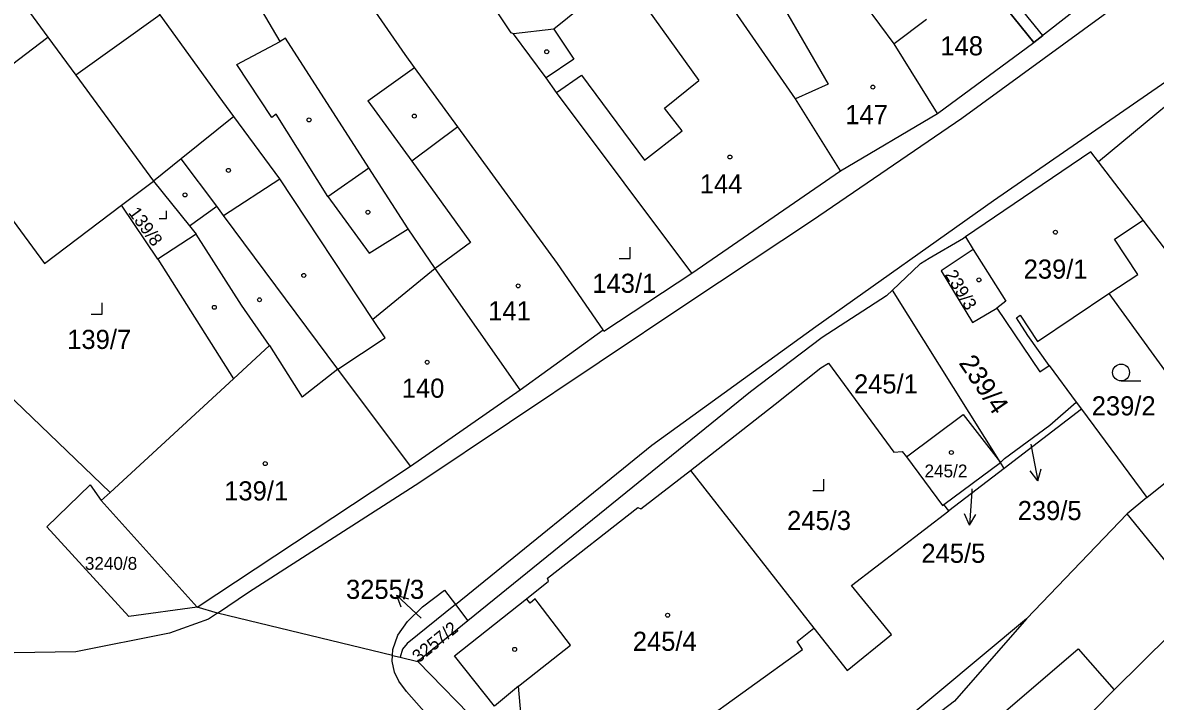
# Model space of a CAD drawing. Extents: x -600849 to -599899, y -1204328 to -1203436.
# Drawn here: x -600587.3 to -600486.5, y -1203787.4 to -1203727 of the extents above; entities that cross this region are included whole.
import ezdxf

# ---------------------------------------------------------------- set-up
doc = ezdxf.new("R2010")
doc.units = 0
for name, color, linetype in [('Vrstva 1', 7, 'Continuous'), ('Vrstva 13', 7, 'Continuous'), ('Vrstva 2', 7, 'Continuous'), ('Vrstva 3', 7, 'Continuous'), ('Vrstva 4', 7, 'Continuous'), ('Vrstva 5', 7, 'Continuous'), ('Vrstva 7', 7, 'Continuous')]:
    doc.layers.add(name, color=color, linetype=linetype)

msp = doc.modelspace()

# ---------------------------------------------------------------- linework, layer by layer
at = {"layer": 'Vrstva 1'}
for p, q in [((-600489.46, -1203722.64), (-600497.34, -1203728.8)), ((-600505.91, -1203735.13), (-600497.34, -1203728.8)), ((-600514.56, -1203740.22), (-600505.91, -1203735.13)), ((-600492.26, -1203738.52), (-600503.41, -1203746.1)), ((-600491.59, -1203739.41), (-600492.26, -1203738.52)), ((-600527.78, -1203749.32), (-600514.56, -1203740.22)), ((-600578.52, -1203743.27), (-600575.69, -1203741.13)), ((-600575.29, -1203748.08), (-600578.52, -1203743.27)), ((-600503.41, -1203746.1), (-600503.6, -1203746.23)), ((-600503.41, -1203746.1), (-600502.75, -1203747.21)), ((-600535.67, -1203754.37), (-600539.73, -1203748.47)), ((-600507.5, -1203748.53), (-600509.92, -1203750.84)), ((-600509.92, -1203750.84), (-600510.46, -1203751.35)), ((-600500.32, -1203766.15), (-600509.92, -1203750.84)), ((-600543.06, -1203759.7), (-600535.67, -1203754.37)), ((-600495.99, -1203757.53), (-600493.58, -1203760.78)), ((-600589.69, -1203759.08), (-600579.54, -1203768.84)), ((-600552.82, -1203766.5), (-600543.06, -1203759.7)), ((-600493.58, -1203760.78), (-600493.1, -1203761.43)), ((-600493.1, -1203761.43), (-600499.98, -1203766.69)), ((-600493.1, -1203761.43), (-600487.29, -1203769.27)), ((-600487.29, -1203769.27), (-600482.45, -1203765.39)), ((-600571.79, -1203779.02), (-600552.82, -1203766.5)), ((-600505.36, -1203769.9), (-600500.32, -1203766.15)), ((-600499.98, -1203766.69), (-600504.92, -1203770.47)), ((-600499.98, -1203766.69), (-600500.32, -1203766.15)), ((-600567.24, -1203777.68), (-600551.99, -1203767.9)), ((-600579.54, -1203768.84), (-600580.33, -1203769.54)), ((-600580.33, -1203769.54), (-600571.79, -1203779.02)), ((-600504.92, -1203770.47), (-600505.36, -1203769.9)), ((-600487.29, -1203769.27), (-600489.05, -1203770.73)), ((-600489.05, -1203770.73), (-600498, -1203780.07)), ((-600482.55, -1203778.7), (-600489.05, -1203770.73)), ((-600569.99, -1203779.55), (-600567.24, -1203777.68)), ((-600548.81, -1203778.78), (-600553.1, -1203782.26)), ((-600548.81, -1203778.78), (-600547.7, -1203780.24)), ((-600569.99, -1203779.55), (-600571.79, -1203779.02)), ((-600554.41, -1203783.32), (-600569.99, -1203779.55)), ((-600547.7, -1203780.24), (-600552.16, -1203783.86)), ((-600554.41, -1203783.32), (-600554.39, -1203782.8)), ((-600554.43, -1203783.82), (-600554.41, -1203783.32)), ((-600554.41, -1203783.32), (-600553.73, -1203783.48)), ((-600553.73, -1203783.48), (-600552.16, -1203783.86)), ((-600552.16, -1203783.86), (-600539.04, -1203797.3))]:
    msp.add_line(p, q, dxfattribs=at)
for points in [[(-600516.74, -1203754.05), (-600500.93, -1203742.85), (-600482.23, -1203729.97), (-600472.33, -1203722.55), (-600463.46, -1203715.87), (-600456.83, -1203710.5), (-600450.71, -1203706.1), (-600424.21, -1203680.79), (-600406.92, -1203664.19), (-600381.77, -1203639.93), (-600378.09, -1203636.25), (-600365.25, -1203624.15), (-600362.86, -1203622.3), (-600356.33, -1203617.3), (-600346.34, -1203609.78), (-600334.21, -1203600.46), (-600309.35, -1203581.63), (-600259.57, -1203537.67), (-600253.46, -1203531.77)], [(-600514.56, -1203740.22), (-600518.55, -1203733.82), (-600530.21, -1203716.96), (-600533.65, -1203713.17), (-600537.95, -1203708.73)], [(-600503.75, -1203735.54), (-600478.6, -1203717.19), (-600468.32, -1203708.8)], [(-600505.91, -1203735.13), (-600509.78, -1203728.93), (-600517.42, -1203718.58), (-600525.04, -1203709.94)], [(-600568.53, -1203735.4), (-600569.85, -1203733.61), (-600575.09, -1203726.34), (-600576.89, -1203723.85), (-600584.83, -1203712.83)], [(-600593, -1203717.54), (-600592.53, -1203718.19), (-600585.08, -1203728.33), (-600582.6, -1203731.71), (-600575.69, -1203741.13)], [(-600527.78, -1203749.32), (-600539.81, -1203733.24), (-600540.75, -1203731.96), (-600543.64, -1203728.03), (-600543.86, -1203727.95), (-600545.87, -1203724.89), (-600548.94, -1203720.23)], [(-600497.34, -1203728.8), (-600501.57, -1203723.53), (-600501.74, -1203723.36)], [(-600603.56, -1203723.74), (-600585.38, -1203748.47), (-600578.52, -1203743.27)], [(-600539.73, -1203748.47), (-600548.6, -1203736.31), (-600552.45, -1203731.03), (-600553.3, -1203729.87), (-600556.63, -1203725.05)], [(-600543.06, -1203759.7), (-600550.62, -1203748.91), (-600553.02, -1203745.37), (-600556.53, -1203739.96), (-600563.93, -1203728.43), (-600564.41, -1203728.72), (-600566.07, -1203725.89)], [(-600480.16, -1203730.41), (-600480.34, -1203730.12), (-600491.59, -1203739.41)], [(-600568.53, -1203735.4), (-600573.22, -1203739.15), (-600575.69, -1203741.13)], [(-600552.82, -1203766.5), (-600559.27, -1203757.85), (-600555.06, -1203755.08), (-600556.15, -1203753.43), (-600564.44, -1203740.94), (-600568.53, -1203735.4)], [(-600551.99, -1203767.9), (-600528.03, -1203751.91), (-600517.03, -1203744.62), (-600503.75, -1203735.54)], [(-600478.21, -1203757.62), (-600484.29, -1203748.96), (-600487.61, -1203744.61), (-600491.59, -1203739.41)], [(-600575.69, -1203741.13), (-600572.49, -1203745.1), (-600571.89, -1203745.84), (-600575.29, -1203748.08)], [(-600503.6, -1203746.23), (-600506.65, -1203748.02), (-600507.43, -1203748.48), (-600507.5, -1203748.53)], [(-600502.75, -1203747.21), (-600505.6, -1203749.1), (-600502.81, -1203753.71), (-600500.62, -1203752.42)], [(-600502.75, -1203747.21), (-600499.84, -1203751.82), (-600500.62, -1203752.42)], [(-600575.29, -1203748.08), (-600568.56, -1203758.71), (-600579.54, -1203768.84)], [(-600535.67, -1203754.37), (-600535.6, -1203754.49), (-600527.78, -1203749.32)], [(-600510.46, -1203751.35), (-600516.19, -1203755.04), (-600522.55, -1203759.86), (-600547.7, -1203780.24)], [(-600495.99, -1203757.53), (-600497.89, -1203754.85), (-600498.89, -1203753.29), (-600498.57, -1203753.07), (-600497.03, -1203755.41), (-600490.66, -1203751.13), (-600481.08, -1203764.32)], [(-600500.62, -1203752.42), (-600496.82, -1203758.09), (-600495.99, -1203757.53)], [(-600548.81, -1203778.78), (-600531.35, -1203764.63), (-600516.74, -1203754.05)], [(-600527.88, -1203766.86), (-600520.35, -1203760.97), (-600516.31, -1203757.75), (-600515.61, -1203757.32), (-600509.8, -1203765.23), (-600509.05, -1203765.18), (-600508.68, -1203765.66)], [(-600500.32, -1203766.15), (-600499.96, -1203765.81), (-600495.92, -1203762.84), (-600493.58, -1203760.78)], [(-600508.68, -1203765.66), (-600503.63, -1203761.88), (-600500.32, -1203766.15)], [(-600508.68, -1203765.66), (-600505.46, -1203769.98), (-600505.36, -1203769.9)], [(-600537.66, -1203796.41), (-600542.87, -1203789.77), (-600543.19, -1203786.06), (-600545.34, -1203787.84), (-600548.91, -1203783.34), (-600542.5, -1203778.28), (-600540.53, -1203776.7), (-600540.63, -1203776.45), (-600532.58, -1203770.15), (-600532.31, -1203770.28), (-600527.88, -1203766.86)], [(-600527.88, -1203766.86), (-600516.91, -1203780.89), (-600513.96, -1203784.67), (-600510.01, -1203781.45), (-600513.57, -1203777.09), (-600504.92, -1203770.47)], [(-600571.79, -1203779.02), (-600577.89, -1203779.86), (-600585.18, -1203771.89), (-600581.32, -1203768.16), (-600580.33, -1203769.54)], [(-600554.39, -1203782.8), (-600553.93, -1203781.52), (-600553.09, -1203780.31), (-600551.73, -1203778.99), (-600549.78, -1203777.5), (-600548.81, -1203778.78)], [(-600482.55, -1203778.7), (-600485.2, -1203781.47), (-600490.18, -1203786.39), (-600492.01, -1203788.21), (-600491.04, -1203789.24), (-600495.44, -1203792.84)], [(-600569.99, -1203779.55), (-600570.79, -1203780.08), (-600574.26, -1203781.35), (-600582.58, -1203783), (-600588.08, -1203783.09), (-600592.09, -1203782.35), (-600596.07, -1203781.08)], [(-600498, -1203780.07), (-600504.41, -1203787.38), (-600510.05, -1203791.68), (-600522.57, -1203801.02), (-600530.25, -1203807.86)], [(-600498, -1203780.07), (-600509.83, -1203789.94), (-600530.22, -1203805.9)], [(-600553.1, -1203782.26), (-600553.51, -1203782.76), (-600553.73, -1203783.48)], [(-600550.94, -1203789.04), (-600553.16, -1203786.52), (-600553.85, -1203785.62), (-600554.23, -1203784.82), (-600554.43, -1203783.82)]]:
    msp.add_lwpolyline(points, dxfattribs=at)
at = {"layer": 'Vrstva 13'}
msp.add_lwpolyline([(-600523.58, -1203699.44), (-600519.95, -1203703.04), (-600518.02, -1203704.91), (-600507.31, -1203717.65), (-600501.74, -1203723.36), (-600501.57, -1203723.53), (-600497.34, -1203728.8), (-600496.55, -1203728.18), (-600500.97, -1203722.73), (-600506.54, -1203717.01), (-600517.25, -1203704.27), (-600519.34, -1203702.25), (-600522.88, -1203698.72)], close=True, dxfattribs=at)
at = {"layer": 'Vrstva 3'}
for p, q in [((-600575.18, -1203744.45), (-600574.51, -1203744.45)), ((-600574.51, -1203744.45), (-600574.51, -1203743.78)), ((-600533.25, -1203748.01), (-600533.25, -1203747.01)), ((-600534.25, -1203748.01), (-600533.25, -1203748.01)), ((-600580.24, -1203752.97), (-600580.24, -1203751.97)), ((-600581.24, -1203752.97), (-600580.24, -1203752.97)), ((-600489.58, -1203758.91), (-600487.83, -1203758.91)), ((-600516.02, -1203768.65), (-600516.02, -1203767.65)), ((-600517.02, -1203768.65), (-600516.02, -1203768.65))]:
    msp.add_line(p, q, dxfattribs=at)
msp.add_circle((-600489.58, -1203758.16), 0.75, dxfattribs=at)
at = {"layer": 'Vrstva 4'}
for p, q in [((-600533.96, -1203722.68), (-600540.06, -1203727.63)), ((-600533.96, -1203722.68), (-600527.15, -1203732.19)), ((-600519.9, -1203725.2), (-600515.63, -1203732.52)), ((-600575.09, -1203726.34), (-600582.6, -1203731.71)), ((-600506.88, -1203726.75), (-600509.78, -1203728.93)), ((-600591.95, -1203733.56), (-600585.08, -1203728.33)), ((-600540.06, -1203727.63), (-600543.64, -1203728.03)), ((-600540.06, -1203727.63), (-600538.27, -1203730.29)), ((-600568.26, -1203730.77), (-600564.41, -1203728.72)), ((-600538.27, -1203730.29), (-600540.75, -1203731.96)), ((-600565.14, -1203735.49), (-600568.26, -1203730.77)), ((-600556.6, -1203733.98), (-600552.45, -1203731.03)), ((-600539.81, -1203733.24), (-600537.59, -1203731.71)), ((-600537.59, -1203731.71), (-600532, -1203739.27)), ((-600530.22, -1203734.64), (-600527.15, -1203732.19)), ((-600515.63, -1203732.52), (-600518.55, -1203733.82)), ((-600556.6, -1203733.98), (-600552.7, -1203739.37)), ((-600528.65, -1203736.65), (-600530.22, -1203734.64)), ((-600564.76, -1203735.17), (-600565.14, -1203735.49)), ((-600560.17, -1203742.51), (-600564.76, -1203735.17)), ((-600548.6, -1203736.31), (-600552.7, -1203739.37)), ((-600532, -1203739.27), (-600528.65, -1203736.65)), ((-600570.05, -1203743.37), (-600573.22, -1203739.15)), ((-600552.7, -1203739.37), (-600547.47, -1203746.6)), ((-600560.17, -1203742.51), (-600556.53, -1203739.96)), ((-600569.45, -1203744.18), (-600564.44, -1203740.94)), ((-600560.17, -1203742.51), (-600556.49, -1203747.54)), ((-600572.49, -1203745.1), (-600570.05, -1203743.37)), ((-600569.45, -1203744.18), (-600570.05, -1203743.37)), ((-600559.27, -1203757.85), (-600569.45, -1203744.18)), ((-600490.16, -1203746.3), (-600487.61, -1203744.61)), ((-600556.49, -1203747.54), (-600553.02, -1203745.37)), ((-600567.86, -1203752.16), (-600571.89, -1203745.84)), ((-600547.47, -1203746.6), (-600550.62, -1203748.91)), ((-600488.09, -1203749.43), (-600490.16, -1203746.3)), ((-600550.62, -1203748.91), (-600556.15, -1203753.43)), ((-600490.66, -1203751.13), (-600488.09, -1203749.43)), ((-600565.37, -1203755.76), (-600567.86, -1203752.16)), ((-600568.56, -1203758.71), (-600565.37, -1203755.76)), ((-600565.37, -1203755.76), (-600562.45, -1203760.35)), ((-600559.27, -1203757.85), (-600562.45, -1203760.35)), ((-600542.17, -1203778.66), (-600542.5, -1203778.28)), ((-600541.73, -1203778.28), (-600542.17, -1203778.66)), ((-600541.46, -1203778.63), (-600541.73, -1203778.28)), ((-600538.56, -1203782.39), (-600541.46, -1203778.63)), ((-600518.4, -1203782.09), (-600516.91, -1203780.89)), ((-600543.19, -1203786.06), (-600538.56, -1203782.39)), ((-600530.25, -1203791.64), (-600517.94, -1203782.8)), ((-600517.94, -1203782.8), (-600518.4, -1203782.09)), ((-600501.31, -1203789.51), (-600493.4, -1203782.72)), ((-600493.4, -1203782.72), (-600490.18, -1203786.39))]:
    msp.add_line(p, q, dxfattribs=at)
at = {"layer": 'Vrstva 5'}
for centre in [(-600540.69, -1203729.63), (-600511.67, -1203732.77), (-600561.84, -1203735.69), (-600552.47, -1203735.35), (-600524.39, -1203738.99), (-600569.01, -1203740.18), (-600572.88, -1203742.36), (-600556.6, -1203743.9), (-600495.42, -1203745.68), (-600562.31, -1203749.52), (-600502.23, -1203749.92), (-600543.23, -1203750.45), (-600566.25, -1203751.69), (-600570.27, -1203752.36), (-600551.33, -1203757.24), (-600504.68, -1203765.27), (-600565.74, -1203766.26), (-600529.93, -1203779.74), (-600543.54, -1203782.78)]:
    msp.add_circle(centre, 0.175, dxfattribs=at)
at = {"layer": 'Vrstva 7'}
for p, q in [((-600497.62, -1203764.53), (-600497.56, -1203764.85)), ((-600497.56, -1203764.85), (-600496.99, -1203767.8)), ((-600496.99, -1203767.8), (-600496.69, -1203766.72)), ((-600496.99, -1203767.8), (-600497.67, -1203766.91)), ((-600502.87, -1203768.75), (-600503.08, -1203771.74)), ((-600502.85, -1203768.49), (-600502.87, -1203768.75)), ((-600503.08, -1203771.74), (-600503.51, -1203770.71)), ((-600503.08, -1203771.74), (-600502.51, -1203770.78)), ((-600551.87, -1203780.01), (-600554.07, -1203777.96)), ((-600554.07, -1203777.96), (-600552.99, -1203778.28)), ((-600554.07, -1203777.96), (-600553.67, -1203779.01))]:
    msp.add_line(p, q, dxfattribs=at)

# ---------------------------------------------------------------- texts
at = {"layer": 'Vrstva 2'}
for s, height, p in [('148', 1.7, (-600505.66, -1203729.95)), ('147', 1.7, (-600514.12, -1203736.07)), ('144', 1.7, (-600527.07, -1203742.23)), ('239/1', 1.7, (-600498.25, -1203749.81)), ('143/1', 1.7, (-600536.63, -1203751.07)), ('141', 1.7, (-600545.9, -1203753.52)), ('139/7', 1.7, (-600583.36, -1203756.06)), ('140', 1.7, (-600553.59, -1203760.4)), ('245/1', 1.7, (-600513.35, -1203760.02)), ('239/2', 1.7, (-600492.19, -1203761.97)), ('245/2', 1.14, (-600507.07, -1203767.48)), ('139/1', 1.7, (-600569.39, -1203769.53)), ('239/5', 1.7, (-600498.78, -1203771.28)), ('245/3', 1.7, (-600519.3, -1203772.16)), ('245/5', 1.7, (-600507.35, -1203775.08)), ('3240/8', 1.139, (-600581.79, -1203775.7)), ('3255/3', 1.7, (-600558.55, -1203778.29)), ('245/4', 1.7, (-600533.03, -1203782.91))]:
    msp.add_text(s, height=height, dxfattribs=at).set_placement(p)
for s, height, rotation, p in [('139/8', 1.14, 306, (-600577.96, -1203743.95)), ('239/3', 1.14, 301, (-600505.29, -1203749.45)), ('239/4', 1.7, 304, (-600504.07, -1203757.31)), ('3257/2', 1.139, 39, (-600552.09, -1203784.03))]:
    msp.add_text(s, height=height, rotation=rotation, dxfattribs=at).set_placement(p)

doc.saveas('drawing.dxf')
